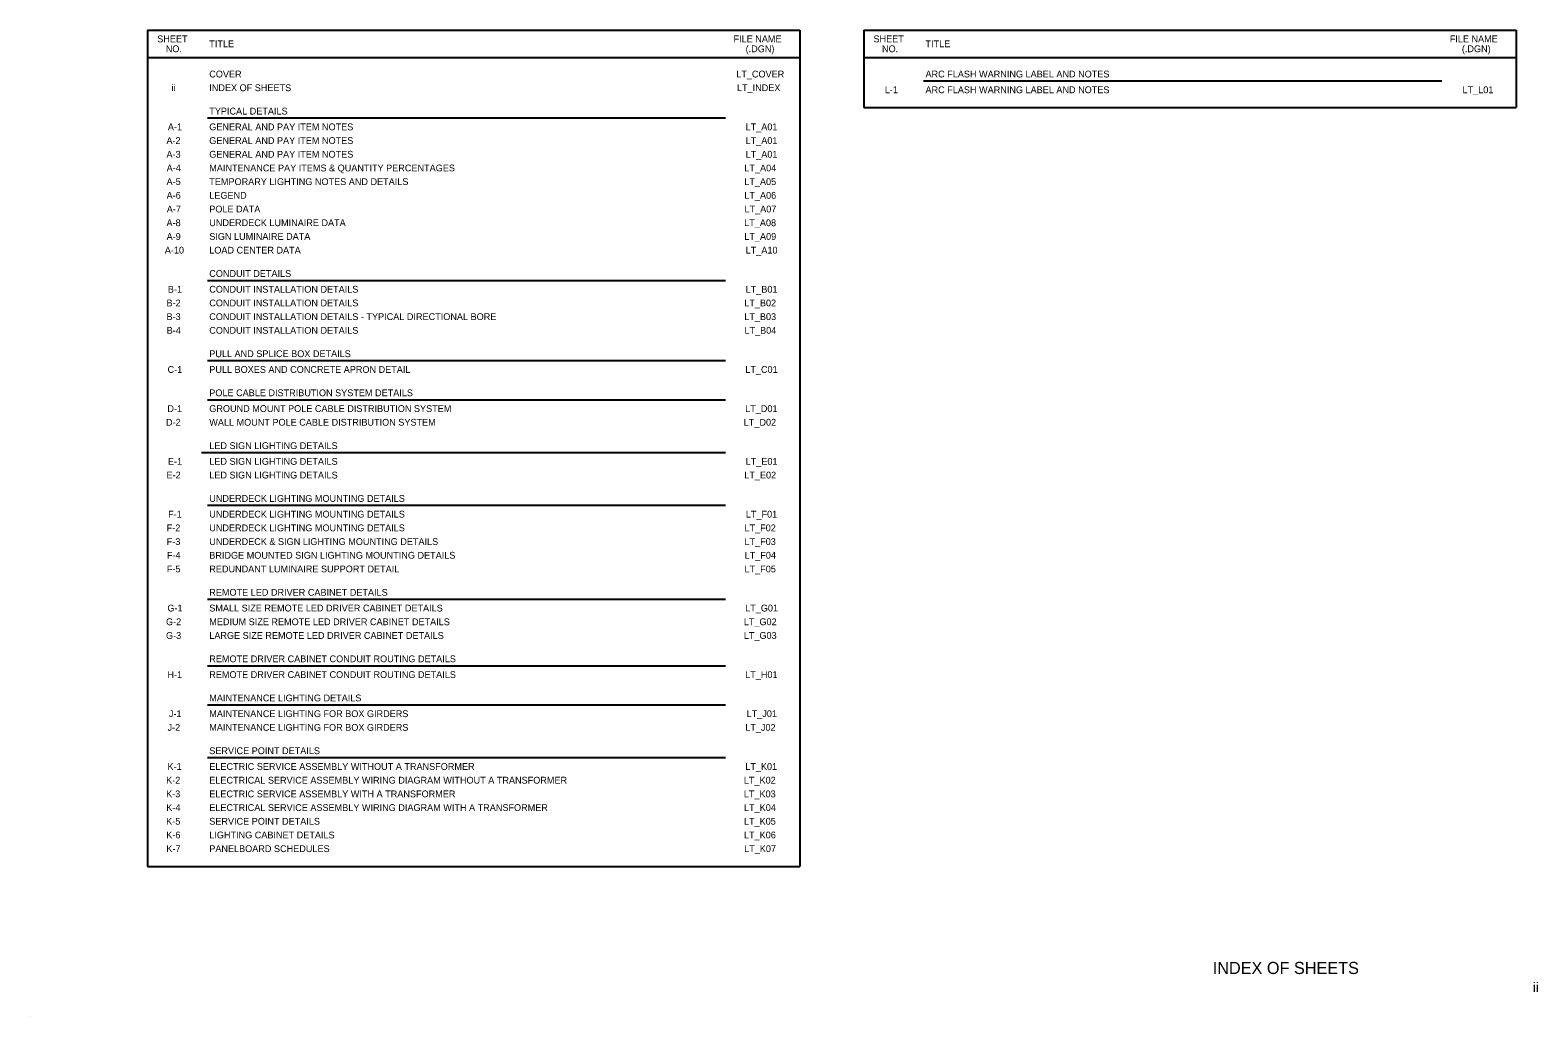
# Model space of a CAD drawing. Extents: x -39 to 737, y -523 to -16.
import ezdxf

# ---------------------------------------------------------------- set-up
doc = ezdxf.new("R2010")
doc.units = 0
for name, color, linetype in [('AdhocPoint_dp', 7, 'Continuous'), ('SumBoxLines_dp', 7, 'Continuous'), ('SumBoxLinesMin_dp', 7, 'Continuous'), ('TextLabel', 7, 'Continuous'), ('TextMisc', 7, 'Continuous'), ('TextShtNo', 7, 'Continuous')]:
    doc.layers.add(name, color=color, linetype=linetype)

msp = doc.modelspace()

# ---------------------------------------------------------------- linework, layer by layer
at = {"layer": 'AdhocPoint_dp'}
msp.add_line((-39.15, -523.47), (-39.15, -523.47), dxfattribs=at)
at = {"layer": 'SumBoxLines_dp'}
for p, q in [((21.27, -29.78), (49.02, -29.78)), ((21.27, -29.78), (356.89, -29.78)), ((52.02, -29.78), (356.89, -29.78)), ((389.8, -29.78), (725.43, -29.78)), ((389.8, -29.78), (725.43, -29.78)), ((420.55, -41.81), (687.18, -41.81)), ((420.55, -41.81), (687.18, -41.81)), ((52.02, -60.88), (318.64, -60.88)), ((52.02, -60.88), (318.64, -60.88)), ((52.02, -144.46), (318.64, -144.46)), ((52.02, -144.46), (318.64, -144.46)), ((52.02, -185.73), (318.64, -185.73)), ((52.02, -185.73), (318.64, -185.73)), ((52.02, -205.86), (318.64, -205.86)), ((52.02, -205.86), (318.64, -205.86)), ((49.02, -233.03), (318.64, -233.03)), ((49.02, -233.03), (318.64, -233.03)), ((52.02, -260.21), (318.64, -260.21)), ((52.02, -260.21), (318.64, -260.21)), ((52.02, -308.53), (318.64, -308.53)), ((52.02, -308.53), (318.64, -308.53)), ((52.02, -342.76), (318.64, -342.76)), ((52.02, -342.76), (318.64, -342.76)), ((52.02, -362.88), (318.64, -362.88)), ((52.02, -362.88), (318.64, -362.88)), ((52.02, -390.06), (318.64, -390.06)), ((52.02, -390.06), (318.64, -390.06))]:
    msp.add_line(p, q, dxfattribs=at)
at = {"layer": 'SumBoxLinesMin_dp'}
for p, q in [((21.27, -15.68), (356.89, -15.68)), ((21.27, -15.68), (21.27, -446.08)), ((356.89, -15.68), (356.89, -446.08)), ((389.8, -15.68), (725.43, -15.68)), ((389.8, -15.68), (389.8, -55.53)), ((725.43, -15.68), (725.43, -55.53)), ((389.8, -55.53), (725.43, -55.53)), ((21.27, -446.08), (356.89, -446.08))]:
    msp.add_line(p, q, dxfattribs=at)

# ---------------------------------------------------------------- texts
at = {"layer": 'TextLabel'}
for s, p in [('SHEET', (26.25, -21.93)), ('TITLE', (53.02, -24.48)), ('FILE NAME', (322.79, -21.93)), ('SHEET', (394.79, -21.93)), ('TITLE', (421.55, -24.48)), ('FILE NAME', (691.33, -21.93)), ('NO.', (30.64, -27.03)), ('(.DGN)', (329.01, -27.03)), ('NO.', (399.18, -27.03)), ('(.DGN)', (697.55, -27.03)), ('COVER', (53.02, -40.03)), ('LT_COVER', (324.18, -40.03)), ('ARC FLASH WARNING LABEL AND NOTES', (421.55, -40.03)), ('ii', (33.61, -47.08)), ('INDEX OF SHEETS', (53.02, -47.08)), ('LT_INDEX', (324.54, -47.08)), ('L-1', (400.62, -48.13)), ('ARC FLASH WARNING LABEL AND NOTES', (421.55, -48.13)), ('LT_L01', (697.9, -48.13)), ('TYPICAL DETAILS', (53.02, -59.11)), ('A-1', (31.7, -67.21)), ('GENERAL AND PAY ITEM NOTES', (53.02, -67.21)), ('LT_A01', (328.99, -67.21)), ('A-2', (30.99, -74.26)), ('GENERAL AND PAY ITEM NOTES', (53.02, -74.26)), ('LT_A01', (328.99, -74.26)), ('A-3', (30.99, -81.31)), ('A-4', (31.08, -88.36)), ('GENERAL AND PAY ITEM NOTES', (53.02, -81.31)), ('MAINTENANCE PAY ITEMS & QUANTITY PERCENTAGES', (53.02, -88.36)), ('LT_A04', (328.36, -88.36)), ('LT_A01', (328.99, -81.31)), ('A-5', (31.03, -95.41)), ('TEMPORARY LIGHTING NOTES AND DETAILS', (53.02, -95.41)), ('LT_A05', (328.31, -95.41)), ('A-6', (31.06, -102.46)), ('LEGEND', (53.02, -102.46)), ('LT_A06', (328.34, -102.46)), ('A-7', (31.14, -109.51)), ('POLE DATA', (53.02, -109.51)), ('LT_A07', (328.43, -109.51)), ('A-8', (31, -116.56)), ('UNDERDECK LUMINAIRE DATA', (53.02, -116.56)), ('LT_A08', (328.28, -116.56)), ('A-9', (31.06, -123.61)), ('SIGN LUMINAIRE DATA', (53.02, -123.61)), ('LT_A09', (328.34, -123.61)), ('A-10', (30.13, -130.66)), ('LOAD CENTER DATA', (53.02, -130.66)), ('LT_A10', (329.03, -130.66)), ('CONDUIT DETAILS', (53.02, -142.68)), ('B-1', (31.72, -150.78)), ('CONDUIT INSTALLATION DETAILS', (53.02, -150.78)), ('LT_B01', (329.01, -150.78)), ('B-2', (31.02, -157.83)), ('CONDUIT INSTALLATION DETAILS', (53.02, -157.83)), ('LT_B02', (328.3, -157.83)), ('B-3', (31.01, -164.88)), ('CONDUIT INSTALLATION DETAILS - TYPICAL DIRECTIONAL BORE', (53.02, -164.88)), ('LT_B03', (328.3, -164.88)), ('B-4', (31.1, -171.93)), ('CONDUIT INSTALLATION DETAILS', (53.02, -171.93)), ('LT_B04', (328.39, -171.93)), ('PULL AND SPLICE BOX DETAILS', (53.02, -183.96)), ('C-1', (31.56, -192.06)), ('PULL BOXES AND CONCRETE APRON DETAIL', (53.02, -192.06)), ('LT_C01', (328.84, -192.06)), ('POLE CABLE DISTRIBUTION SYSTEM DETAILS', (53.02, -204.08)), ('D-1', (31.46, -212.18)), ('GROUND MOUNT POLE CABLE DISTRIBUTION SYSTEM', (53.02, -212.18)), ('LT_D01', (328.75, -212.18)), ('D-2', (30.75, -219.23)), ('WALL MOUNT POLE CABLE DISTRIBUTION SYSTEM', (53.02, -219.23)), ('LT_D02', (328.04, -219.23)), ('LED SIGN LIGHTING DETAILS', (53.02, -231.26)), ('E-1', (31.74, -239.36)), ('LED SIGN LIGHTING DETAILS', (53.02, -239.36)), ('LT_E01', (329.02, -239.36)), ('E-2', (31.03, -246.41)), ('LED SIGN LIGHTING DETAILS', (53.02, -246.41)), ('LT_E02', (328.31, -246.41)), ('UNDERDECK LIGHTING MOUNTING DETAILS', (53.02, -258.43)), ('F-1', (31.84, -266.53)), ('UNDERDECK LIGHTING MOUNTING DETAILS', (53.02, -266.53)), ('LT_F01', (329.12, -266.53)), ('F-2', (31.13, -273.58)), ('UNDERDECK LIGHTING MOUNTING DETAILS', (53.02, -273.58)), ('LT_F02', (328.41, -273.58)), ('F-3', (31.12, -280.63)), ('UNDERDECK & SIGN LIGHTING MOUNTING DETAILS', (53.02, -280.63)), ('LT_F03', (328.41, -280.63)), ('F-4', (31.22, -287.68)), ('BRIDGE MOUNTED SIGN LIGHTING MOUNTING DETAILS', (53.02, -287.68)), ('LT_F04', (328.5, -287.68)), ('F-5', (31.17, -294.73)), ('REDUNDANT LUMINAIRE SUPPORT DETAIL', (53.02, -294.73)), ('LT_F05', (328.45, -294.73)), ('REMOTE LED DRIVER CABINET DETAILS', (53.02, -306.76)), ('G-1', (31.49, -314.86)), ('SMALL SIZE REMOTE LED DRIVER CABINET DETAILS', (53.02, -314.86)), ('LT_G01', (328.77, -314.86)), ('G-2', (30.78, -321.91)), ('G-3', (30.77, -328.96)), ('MEDIUM SIZE REMOTE LED DRIVER CABINET DETAILS', (53.02, -321.91)), ('LARGE SIZE REMOTE LED DRIVER CABINET DETAILS', (53.02, -328.96)), ('LT_G03', (328.06, -328.96)), ('LT_G02', (328.06, -321.91)), ('REMOTE DRIVER CABINET CONDUIT ROUTING DETAILS', (53.02, -340.98)), ('H-1', (31.51, -349.08)), ('REMOTE DRIVER CABINET CONDUIT ROUTING DETAILS', (53.02, -349.08)), ('LT_H01', (328.79, -349.08)), ('MAINTENANCE LIGHTING DETAILS', (53.02, -361.11)), ('J-1', (32.24, -369.21)), ('MAINTENANCE LIGHTING FOR BOX GIRDERS', (53.02, -369.21)), ('LT_J01', (329.52, -369.21)), ('J-2', (31.53, -376.26)), ('MAINTENANCE LIGHTING FOR BOX GIRDERS', (53.02, -376.26)), ('LT_J02', (328.81, -376.26)), ('SERVICE POINT DETAILS', (53.02, -388.28)), ('K-1', (31.52, -396.38)), ('ELECTRIC SERVICE ASSEMBLY WITHOUT A TRANSFORMER', (53.02, -396.38)), ('LT_K01', (328.81, -396.38)), ('K-2', (30.81, -403.43)), ('ELECTRICAL SERVICE ASSEMBLY WIRING DIAGRAM WITHOUT A TRANSFORMER', (53.02, -403.43)), ('LT_K02', (328.1, -403.43)), ('K-3', (30.81, -410.48)), ('ELECTRIC SERVICE ASSEMBLY WITH A TRANSFORMER', (53.02, -410.48)), ('LT_K03', (328.09, -410.48)), ('K-4', (30.9, -417.53)), ('ELECTRICAL SERVICE ASSEMBLY WIRING DIAGRAM WITH A TRANSFORMER', (53.02, -417.53)), ('LT_K04', (328.18, -417.53)), ('K-5', (30.85, -424.58)), ('SERVICE POINT DETAILS', (53.02, -424.58)), ('LT_K05', (328.14, -424.58)), ('K-6', (30.88, -431.63)), ('LIGHTING CABINET DETAILS', (53.02, -431.63)), ('LT_K06', (328.16, -431.63)), ('K-7', (30.96, -438.68)), ('PANELBOARD SCHEDULES', (53.02, -438.68)), ('LT_K07', (328.25, -438.68))]:
    msp.add_text(s, height=3.5, dxfattribs=at).set_placement(p)
at = {"layer": 'TextMisc'}
msp.add_text('       INDEX OF SHEETS         ', height=6.25, dxfattribs=at).set_placement((553.1, -501.43))
at = {"layer": 'TextShtNo'}
msp.add_text('  ii  ', height=5, dxfattribs=at).set_placement((730.42, -510.72))

doc.saveas('drawing.dxf')
